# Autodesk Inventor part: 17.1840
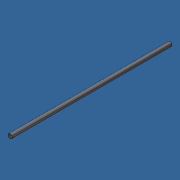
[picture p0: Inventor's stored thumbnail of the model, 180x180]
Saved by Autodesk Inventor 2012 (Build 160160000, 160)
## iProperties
Created: 2007-07
Part Number: 17.1840
Material: Steel
Document SubType Name: Modeling
Designer: Andy Moles
Density: 7.85 g/cm^3
Description: 8mm DIA STEEL ROD  LENGTH = SPECIFY +/- 1/32"
Mass: 116.402 g
Surface Area: 75.1469 cm^2
Volume: 14.8283 cm^3
Vendor: F
Author: Andy Moles
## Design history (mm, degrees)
sketch "Sketch1"
  geometry: C1 r 4 at (0, 0); 1 further point
  constraints: 1 centre point, 1 coincident
  dimensions: "d0" = 8 diameter of C1
extrude "Extrusion1" new body sketch "Sketch1" stored distance "d1" = 295 (= ROD_LENGTH); taper "d2" = 0 deg
body "Solid1"
other parameters: "ROD_LENGTH" = 295 (computed from FRAME_ID) [user parameter; used in 1 equation term]
